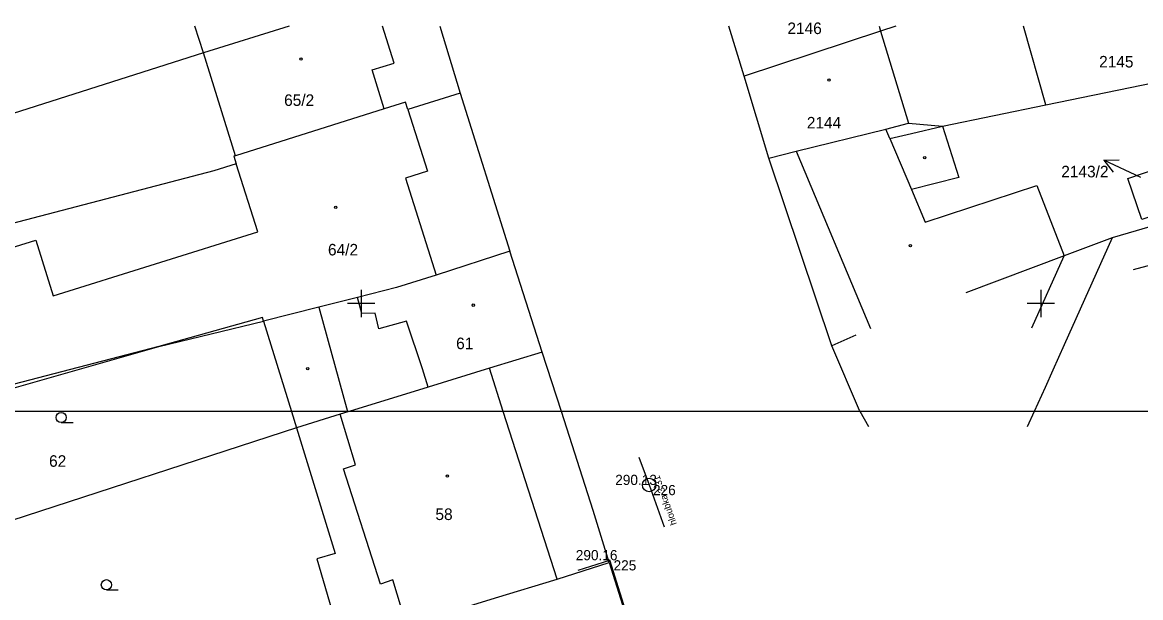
# Model space of a CAD drawing. Extents: x -599866 to -590076, y -1178039 to -1154526.
# Drawn here: x -599724.9 to -599642.7, y -1154571.7 to -1154529.3 of the extents above; entities that cross this region are included whole.
import ezdxf

# ---------------------------------------------------------------- set-up
doc = ezdxf.new("R2010")
doc.units = 0
for name, color, linetype in [('Budovy', 7, 'Continuous'), ('IS kanalizace', 7, 'Continuous'), ('IS neurčené', 7, 'Continuous'), ('KN', 7, 'Continuous'), ('Popisy', 7, 'Continuous'), ('Rám', 7, 'Continuous'), ('Vrstva 5', 7, 'Continuous'), ('Vrstva 58', 7, 'Continuous'), ('Vrstva 59', 7, 'Continuous'), ('Vrstva 60', 7, 'Continuous')]:
    doc.layers.add(name, color=color, linetype=linetype)

msp = doc.modelspace()

# ---------------------------------------------------------------- linework, layer by layer
at = {"layer": 'Budovy'}
msp.add_line((-599684.043, -1154569.63), (-599681.71, -1154568.9), dxfattribs=at)
msp.add_lwpolyline([(-599676.33, -1154586.25), (-599678.67, -1154578.62), (-599681.71, -1154568.9)], dxfattribs=at)
at = {"layer": 'IS kanalizace'}
for points in [[(-599679.57, -1154561.32), (-599678.81, -1154563.36)], [(-599678.81, -1154563.36), (-599677.7, -1154566.43)]]:
    msp.add_lwpolyline(points, dxfattribs=at)
at = {"layer": 'IS neurčené'}
msp.add_circle((-599678.81, -1154563.36), 0.5, dxfattribs=at)
at = {"layer": 'KN'}
for p, q in [((-599711.61, -1154531.55), (-599712.235, -1154529.575)), ((-599697.57, -1154532.3), (-599698.432, -1154529.575)), ((-599694.221, -1154529.575), (-599692.71, -1154534.5)), ((-599671.83, -1154533.26), (-599672.941, -1154529.575)), ((-599661.89, -1154529.575), (-599661.78, -1154529.94)), ((-599649.63, -1154535.37), (-599651.261, -1154529.575)), ((-599661.78, -1154529.94), (-599659.73, -1154536.73)), ((-599711.61, -1154531.55), (-599757.79, -1154546.22)), ((-599709.25, -1154539.12), (-599711.61, -1154531.55)), ((-599699.19, -1154532.79), (-599697.57, -1154532.3)), ((-599698.31, -1154535.67), (-599699.19, -1154532.79)), ((-599649.63, -1154535.37), (-599637.02, -1154532.76)), ((-599670.01, -1154539.29), (-599671.83, -1154533.26)), ((-599692.71, -1154534.5), (-599696.56, -1154535.72)), ((-599692.71, -1154534.5), (-599689.07, -1154546.14)), ((-599696.56, -1154535.72), (-599695.12, -1154540.26)), ((-599661.11, -1154537.86), (-599661.41, -1154537.15)), ((-599659.51, -1154537.48), (-599657.22, -1154536.94)), ((-599657.22, -1154536.94), (-599656.03, -1154540.71)), ((-599661.11, -1154537.86), (-599659.51, -1154537.48)), ((-599661.11, -1154537.86), (-599659.52, -1154541.61)), ((-599670.01, -1154539.29), (-599668, -1154538.79)), ((-599668, -1154538.79), (-599662.53, -1154551.84)), ((-599665.38, -1154553.11), (-599670.01, -1154539.29)), ((-599645.36, -1154539.442), (-599644.241, -1154539.411)), ((-599642.64, -1154540.71), (-599645.36, -1154539.442)), ((-599645.36, -1154539.442), (-599644.664, -1154540.319)), ((-599695.12, -1154540.26), (-599696.75, -1154540.78)), ((-599696.75, -1154540.78), (-599694.49, -1154547.9)), ((-599656.03, -1154540.71), (-599659.52, -1154541.61)), ((-599658.5, -1154544), (-599650.3, -1154541.32)), ((-599650.3, -1154541.32), (-599648.27, -1154546.48)), ((-599659.52, -1154541.61), (-599658.5, -1154544)), ((-599639.06, -1154543.48), (-599644.75, -1154545.16)), ((-599686.68, -1154553.57), (-599689.07, -1154546.14)), ((-599643.17, -1154547.49), (-599638.19, -1154546.17)), ((-599650.65, -1154551.8), (-599648.27, -1154546.48)), ((-599699.96, -1154550.74), (-599700.26, -1154549.55)), ((-599703.11, -1154550.27), (-599700.998, -1154557.95)), ((-599707.26, -1154551.02), (-599714.88, -1154553.16)), ((-599707.18, -1154551.3), (-599707.26, -1154551.02)), ((-599698.98, -1154550.71), (-599699.96, -1154550.74)), ((-599698.69, -1154551.87), (-599698.98, -1154550.71)), ((-599714.88, -1154553.16), (-599707.18, -1154551.3)), ((-599707.18, -1154551.3), (-599705.127, -1154557.95)), ((-599696.66, -1154551.3), (-599698.69, -1154551.87)), ((-599695.5, -1154554.8), (-599696.66, -1154551.3)), ((-599663.61, -1154552.33), (-599665.38, -1154553.11)), ((-599685.27, -1154557.95), (-599686.68, -1154553.57)), ((-599695.07, -1154556.16), (-599695.5, -1154554.8)), ((-599689.542, -1154557.95), (-599690.56, -1154554.77)), ((-599705.127, -1154557.95), (-599704.76, -1154559.14)), ((-599700.41, -1154561.87), (-599701.54, -1154558.15)), ((-599700.998, -1154557.95), (-599700.99, -1154557.98)), ((-599685.59, -1154570.3), (-599689.542, -1154557.95)), ((-599682.92, -1154565.25), (-599685.27, -1154557.95)), ((-599704.76, -1154559.14), (-599739.29, -1154570.4)), ((-599722.076, -1154558.77), (-599721.201, -1154558.77)), ((-599701.29, -1154562.16), (-599700.41, -1154561.87)), ((-599698.58, -1154570.65), (-599701.29, -1154562.16)), ((-599681.75, -1154569.06), (-599682.92, -1154565.25)), ((-599681.75, -1154569.06), (-599678.7, -1154578.71)), ((-599697.67, -1154570.35), (-599698.58, -1154570.65)), ((-599696.65, -1154573.69), (-599697.67, -1154570.35)), ((-599718.747, -1154571.08), (-599717.872, -1154571.08))]:
    msp.add_line(p, q, dxfattribs=at)
for points in [[(-599705.305, -1154529.575), (-599711.61, -1154531.55)], [(-599660.676, -1154529.575), (-599661.78, -1154529.94), (-599671.83, -1154533.26)], [(-599696.56, -1154535.72), (-599696.74, -1154535.17), (-599698.31, -1154535.67), (-599709.25, -1154539.12)], [(-599668, -1154538.79), (-599661.41, -1154537.15), (-599659.73, -1154536.73), (-599657.22, -1154536.94), (-599649.63, -1154535.37)], [(-599709.19, -1154539.72), (-599710.84, -1154540.22), (-599745.47, -1154549.29), (-599755.69, -1154552.79)], [(-599714.88, -1154553.16), (-599732.72, -1154557.8), (-599733.57, -1154555.04), (-599729.92, -1154554.02), (-599731.84, -1154547.79), (-599723.93, -1154545.34), (-599722.65, -1154549.43), (-599707.6, -1154544.72), (-599709.19, -1154539.72)], [(-599709.25, -1154539.12), (-599709.37, -1154539.16), (-599709.19, -1154539.72)], [(-599638.88, -1154542.56), (-599642.57, -1154543.81), (-599643.6, -1154540.79), (-599638.2, -1154538.95)], [(-599644.75, -1154545.16), (-599648.27, -1154546.48), (-599655.51, -1154549.21)], [(-599644.75, -1154545.16), (-599648.28, -1154553.04), (-599649.11, -1154554.9), (-599649.68, -1154556.18), (-599650.49, -1154557.95)], [(-599689.07, -1154546.14), (-599694.49, -1154547.9), (-599697.4, -1154548.83), (-599700.26, -1154549.55), (-599703.11, -1154550.27), (-599707.18, -1154551.3)], [(-599731.839, -1154557.95), (-599726.4, -1154556.44), (-599714.88, -1154553.16)], [(-599686.68, -1154553.57), (-599690.56, -1154554.77), (-599695.07, -1154556.16), (-599700.892, -1154557.95)], [(-599663.29, -1154557.95), (-599663.33, -1154557.88), (-599665.38, -1154553.11)], [(-599700.892, -1154557.95), (-599700.99, -1154557.98), (-599701.54, -1154558.15), (-599704.76, -1154559.14)], [(-599662.65, -1154559.08), (-599663.29, -1154557.95)], [(-599650.49, -1154557.95), (-599651.007, -1154559.08)], [(-599704.76, -1154559.14), (-599701.91, -1154568.4), (-599703.26, -1154568.8), (-599701.39, -1154575.17)], [(-599701.39, -1154575.17), (-599696.65, -1154573.69), (-599690.11, -1154571.66), (-599685.59, -1154570.3), (-599681.75, -1154569.06)]]:
    msp.add_lwpolyline(points, dxfattribs=at)
for centre, radius in [((-599704.433, -1154532), 0.0875), ((-599665.583, -1154533.55), 0.0875), ((-599658.533, -1154539.27), 0.0875), ((-599701.873, -1154542.91), 0.0875), ((-599659.593, -1154545.74), 0.0875), ((-599691.753, -1154550.12), 0.0875), ((-599703.933, -1154554.79), 0.0875), ((-599722.076, -1154558.395), 0.375), ((-599693.653, -1154562.7), 0.0875), ((-599718.746, -1154570.705), 0.375)]:
    msp.add_circle(centre, radius, dxfattribs=at)
at = {"layer": 'Rám'}
for points in [[(-599701.74, -1154557.95), (-599806.74, -1154557.95)], [(-599596.74, -1154557.95), (-599701.74, -1154557.95)]]:
    msp.add_lwpolyline(points, dxfattribs=at)
at = {"layer": 'Vrstva 5'}
for p, q in [((-599700, -1154549), (-599700, -1154551)), ((-599650, -1154549), (-599650, -1154551)), ((-599699, -1154550), (-599701, -1154550)), ((-599649, -1154550), (-599651, -1154550))]:
    msp.add_line(p, q, dxfattribs=at)
at = {"layer": 'Vrstva 60'}
for p, q in [((-599678.81, -1154563.36), (-599678.81, -1154563.36)), ((-599681.71, -1154568.9), (-599681.71, -1154568.9))]:
    msp.add_line(p, q, dxfattribs=at)

# ---------------------------------------------------------------- texts
at = {"layer": 'KN'}
for s, p in [('2146', (-599668.642, -1154530.16)), ('2145', (-599645.709, -1154532.62)), ('65/2', (-599705.669, -1154535.45)), ('2144', (-599667.212, -1154537.11)), ('2143/2', (-599648.492, -1154540.71)), ('64/2', (-599702.442, -1154546.46)), ('61', (-599693.014, -1154553.36)), ('62', (-599722.963, -1154562.02)), ('58', (-599694.536, -1154565.94))]:
    msp.add_text(s, height=0.85, dxfattribs=at).set_placement(p)
at = {"layer": 'Popisy'}
msp.add_text('hloubka 3,31', height=0.5, rotation=109.87814, dxfattribs=at).set_placement((-599676.766, -1154566.219))
at = {"layer": 'Vrstva 58'}
for s, p in [('290.13 ', (-599681.31, -1154563.36)), ('290.16 ', (-599684.21, -1154568.9))]:
    msp.add_text(s, height=0.75, dxfattribs=at).set_placement(p)
at = {"layer": 'Vrstva 59'}
for s, p in [(' 226', (-599678.81, -1154564.11)), (' 225', (-599681.71, -1154569.65))]:
    msp.add_text(s, height=0.75, dxfattribs=at).set_placement(p)

doc.saveas('drawing.dxf')
